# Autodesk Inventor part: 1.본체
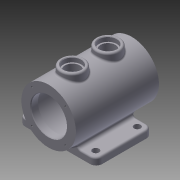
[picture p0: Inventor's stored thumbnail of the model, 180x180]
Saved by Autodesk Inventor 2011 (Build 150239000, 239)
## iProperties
Created: 2015-04
Part Number: 1.본체
Document SubType Name: Modeling
Designer: user
Density: 2.71 g/cm^3
Material: 알루미늄-6061
Mass: 1283.67 g
Surface Area: 1047 cm^2
Volume: 473.679 cm^3
Author: user
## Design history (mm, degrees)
sketch "스케치1"
  geometry: L1 (-65, 47.5)-(65, 47.5); L2 (65, 47.5)-(65, -47.5); L3 (65, -47.5)-(-65, -47.5); L4 (-65, -47.5)-(-65, 47.5); 3 further points
  constraints: 8 end point, 2 midpoint, 2 parallel, 1 horizontal, 1 horizontal alignment, 1 perpendicular, 1 vertical alignment
  dimensions: "d0" = 130 distance of L2.end L3.end; "d1" = 95 distance of L1.end L2.end
extrude "돌출1" new body sketch "스케치1" distance "d2" = 12; taper "d3" = 0 deg
sketch "스케치2"
  geometry: L1 (47.5, 12)-(47.5, 0) reference; L2 (47.5, 0)-(-47.5, 0) reference; L3 (-47.5, 0)-(-47.5, 12) reference; L4 (-47.5, 12)-(47.5, 12) reference; L5 (77.5, 50)-(-62.5, 50); L6 (77.5, 96)-(-62.5, 96); L7 (77.5, 96)-(77.5, 80); L8 (77.5, 80)-(65.5, 80); L9 (65.5, 80)-(65.5, 87.5); L10 (65.5, 87.5)-(-50.5, 87.5); L11 (-50.5, 87.5)-(-50.5, 80); L12 (-50.5, 80)-(-62.5, 80); L13 (-62.5, 80)-(-62.5, 96); 1 further point
  constraints: 18 end point, 5 parallel, 2 perpendicular, 2 vertical alignment, 1 collinear, 1 horizontal alignment
  dimensions: "d4" = 50 vertical distance of L2.end L5.end; "d5" = 140 distance of L5.start L5.end; "d6" = 15 horizontal distance of L3.end L5.end; "d7" = 12 distance of L7.end L8.end; "d8" = 12 distance of L11.end L12.end; "d9" = 60 diameter of L12 L5; "d10" = 75 diameter of L10 L5; "d12" = 92 diameter of L6 L5
revolve "회전1" sketch "스케치2" stored, may be unused: angle "d13" = 90 deg
node "작업 평면1"
sketch "스케치3"
  geometry: L1 (0, -70)-(0, 70) reference; C1 r 20 at (0, 30); C2 r 20 at (0, -30); 3 further points
  constraints: 3 point on line, 2 centre point, 2 coincident
  dimensions: "d14" = 40 distance of point (0, 30) L1.end; "d15" = 40 distance of L1.start point (0, -30); "d16" = 40 diameter of C1; "d17" = 40 diameter of C2
extrude "돌출2" join sketch "스케치3" distance "d18" = 10; taper "d19" = 0 deg
sketch "스케치4"
  geometry: L1 (0, -50)-(0, -10) reference; A1 r 20 centre (0, -30) between (0, -10) and (0, -50) reference; 1 further point
extrude "돌출3" join sketch "스케치4" stored distance "d20" = 10; taper "d21" = 0 deg
sketch "스케치5"
  geometry: L1 (0, -50)-(0, -10) reference; A1 r 20 centre (0, -30) between (0, -50) and (0, -10) reference; 1 further point
extrude "돌출4" join sketch "스케치5" stored distance "d22" = 10; taper "d23" = 0 deg
sketch "스케치6"
  geometry: L1 (0, 10)-(0, 50) reference; A1 r 20 centre (0, 30) between (0, 10) and (0, 50) reference; 1 further point
extrude "돌출5" join sketch "스케치6" stored distance "d24" = 10; taper "d25" = 0 deg
sketch "스케치7"
  geometry: L1 (0, 10)-(0, 50) reference; A1 r 20 centre (0, 30) between (0, 50) and (0, 10) reference; 1 further point
extrude "돌출6" join sketch "스케치7" stored distance "d26" = 8; taper "d27" = 0 deg
sketch "스케치8"
  geometry: C1 r 20 at (0, 0) reference; C2 r 15 at (0, 0); 1 further point
  constraints: 1 centre point, 1 coincident
  dimensions: "d28" = 30 diameter of C2
extrude "돌출7" cut sketch "스케치8" distance "d29" = 8; taper "d30" = 0 deg
sketch "스케치9"
  geometry: C1 r 15 at (0, 0) reference; C2 r 12.5 at (0, 0); 1 further point
  constraints: 1 centre point, 1 coincident
  dimensions: "d31" = 25 diameter of C2
extrude "돌출8" cut sketch "스케치9" stored distance "d32" = 8; taper "d33" = 0 deg
sketch "스케치10"
  geometry: C1 r 20 at (0, 0) reference; C2 r 15 at (0, 0); 1 further point
  constraints: 1 centre point, 1 coincident
  dimensions: "d34" = 30 diameter of C2
extrude "돌출9" cut sketch "스케치10" distance "d35" = 8; taper "d36" = 0 deg
sketch "스케치11"
  geometry: C1 r 15 at (0, 0) reference; C2 r 12.5 at (0, 0); 1 further point
  constraints: 1 centre point, 1 coincident
  dimensions: "d37" = 25 diameter of C2
extrude "돌출10" cut sketch "스케치11" stored distance "d38" = 8; taper "d39" = 0 deg
sketch "스케치12" dims "d40" = 80
  geometry: L1 (0, 0)-(28.284, 28.284); L2 (0, 0)-(40, 0); C1 r 30 at (0, 0) reference; 2 further points
  constraints: 4 end point, 2 coincident, 1 equal length, 1 horizontal, 3 other
  dimensions: "d41" = 45 deg angle of L2 L1
hole "Hole1" sketch "스케치12" at (28.284, 28.284) diameter "d42" = 3.242; stored, may be unused: countersink angle "d46" = 90 deg, drill point angle "d48" = 118 deg; dims "d43" = 8, "d44" = 4, "d45" = 2, "d47" = 10
node "작업 평면2"
fillet "모깎기2" dims "d53" = 10
fillet "모깎기3" dims "d54" = 10
fillet "모깎기4" dims "d61" = 3
fillet "모깎기5" dims "d62" = 3
fillet "모깎기6" dims "d63" = 5
fillet "모깎기7" dims "d64" = 3
fillet "모깎기8" dims "d65" = 3
chamfer "모따기2" distance "d69" = 1; stored, may be unused: second distance "d70" = 2, angle "d71" = 45 deg
sketch "스케치16"
  geometry: L1 (55, 47.5)-(-55, 47.5) reference; L2 (52, 35)-(-52, 35); C1 r 5.5 at (52, 35); C2 r 5.5 at (-52, 35); 3 further points
  constraints: 2 centre point, 2 end point, 2 midpoint, 1 parallel, 1 vertical alignment
  dimensions: "d75" = 11 diameter of C1; "d76" = 11 diameter of C2; "d77" = 104 distance of L2.end L2.start; "d78" = 12.5 distance between parallel lines of L1 L2
extrude "돌출13" cut sketch "스케치16" stored distance "d79" = 8; taper "d80" = 0 deg
sketch "스케치17"
  geometry: L1 (-62, -37.5)-(-62, 37.5) reference; L2 (-45.989, 21.757)-(-45.989, -21.757); L3 (-45.989, -21.757)-(-62.011, -21.757); L4 (-62.011, -21.757)-(-62.011, 21.757); L5 (-62.011, 21.757)-(-45.989, 21.757); L6 (-45.989, 21.757)-(-62.011, 21.757); L7 (-62.011, 21.757)-(-62.011, -21.757); L8 (-62.011, -21.757)-(-45.989, -21.757); L9 (-45.989, -21.757)-(-45.989, 21.757); L10 (-45.989, 21.757)-(-62.011, -21.757); L11 (-45.989, -21.757)-(-62.011, 21.757); C1 r 5.5 at (-52, 35) reference; 2 further points
  constraints: 12 end point, 2 parallel, 1 horizontal, 1 midpoint, 1 perpendicular, 2 other
  dimensions: "d81" = 35 vertical distance of C1.centre point (-54, 0); "d82" = 8 distance from line of L1 point (-54, 0)
feature "엠보싱1" sketch "스케치17" dims "d0" = 130, "d1" = 95, "d83" = 1, "d84" = 0
sketch "스케치18"
  geometry: 1 further point
chamfer "모따기3" distance "d85" = 1; stored, may be unused: second distance "d86" = 2, angle "d87" = 45 deg
node "솔리드1"
pattern_circular "원형 패턴1" dims angle "d50" = 360 deg
mirror "대칭1"
mirror "대칭3"
node "작업 평면4"
node "절단 모서리 투영1"
node "절단 모서리 투영2"
